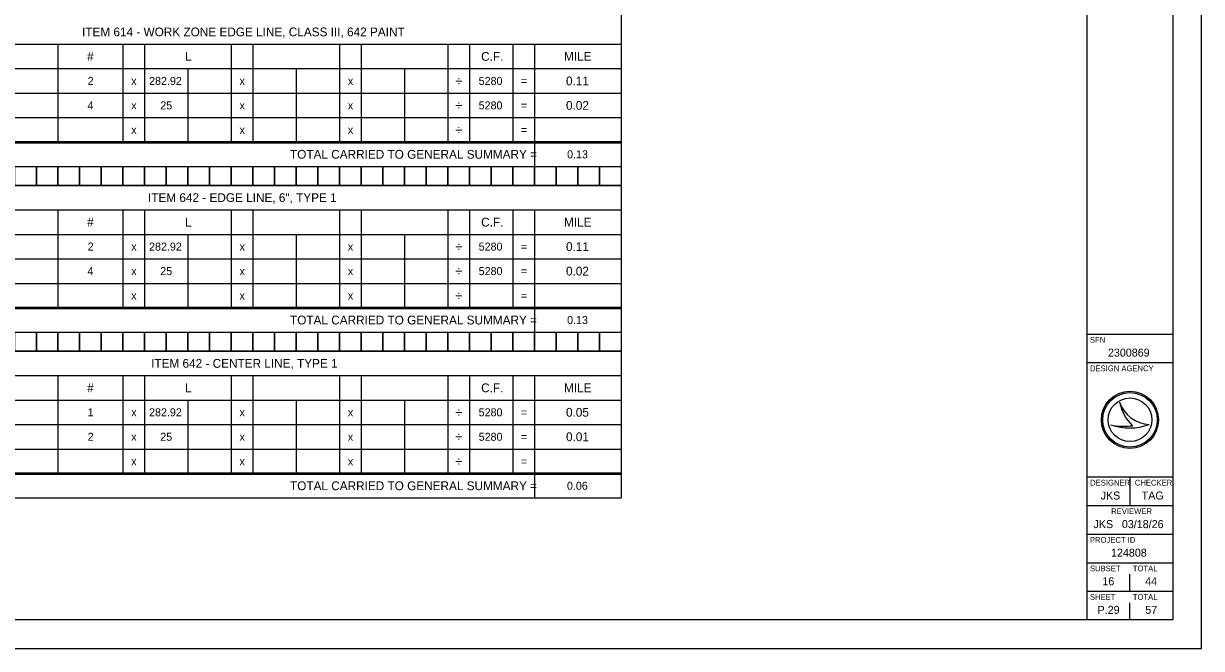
# Model space of a CAD drawing. Extents: x 0 to 34, y 0 to 22.
# Drawn here: x 13.4 to 34, y 0 to 10.93 of the extents above; entities that cross this region are included whole.
import ezdxf

# ---------------------------------------------------------------- set-up
doc = ezdxf.new("R2010")
doc.units = 0
for name, color, linetype in [('Default', 7, 'Continuous'), ('SH_Border', 7, 'Continuous'), ('SH_Cut_Line', 7, 'Continuous'), ('SH_Data', 7, 'Continuous')]:
    doc.layers.add(name, color=color, linetype=linetype)

msp = doc.modelspace()

# ---------------------------------------------------------------- linework, layer by layer
at = {"layer": 'Default'}
for p, q in [((23.854, 11.768), (23.854, 8.847)), ((10.595, 10.571), (23.854, 10.571)), ((14.004, 10.571), (14.004, 8.869)), ((15.141, 10.571), (15.141, 8.869)), ((15.52, 10.571), (15.52, 8.869)), ((17.035, 10.571), (17.035, 8.869)), ((17.414, 10.571), (17.414, 8.869)), ((18.929, 10.571), (18.929, 8.869)), ((19.308, 10.571), (19.308, 8.869)), ((20.823, 10.571), (20.823, 8.869)), ((21.202, 10.571), (21.202, 8.869)), ((21.96, 10.571), (21.96, 8.869)), ((22.339, 10.571), (22.339, 8.869)), ((10.595, 10.143), (23.854, 10.143)), ((16.277, 10.143), (16.277, 8.869)), ((18.171, 10.143), (18.171, 8.869)), ((20.066, 10.143), (20.066, 8.869)), ((10.595, 9.714), (23.854, 9.714)), ((10.595, 9.286), (23.854, 9.286)), ((10.595, 8.869), (23.854, 8.869)), ((23.854, 8.869), (23.854, 5.948)), ((10.595, 8.847), (23.854, 8.847)), ((22.339, 8.847), (22.339, 8.43)), ((10.595, 8.43), (23.854, 8.43)), ((10.595, 8.1), (23.854, 8.1)), ((10.595, 7.672), (23.854, 7.672)), ((14.004, 7.672), (14.004, 5.97)), ((15.141, 7.672), (15.141, 5.97)), ((15.52, 7.672), (15.52, 5.97)), ((17.035, 7.672), (17.035, 5.97)), ((17.414, 7.672), (17.414, 5.97)), ((18.929, 7.672), (18.929, 5.97)), ((19.308, 7.672), (19.308, 5.97)), ((20.823, 7.672), (20.823, 5.97)), ((21.202, 7.672), (21.202, 5.97)), ((21.96, 7.672), (21.96, 5.97)), ((22.339, 7.672), (22.339, 5.97)), ((10.595, 7.244), (23.854, 7.244)), ((16.277, 7.244), (16.277, 5.97)), ((18.171, 7.244), (18.171, 5.97)), ((20.066, 7.244), (20.066, 5.97)), ((10.595, 6.816), (23.854, 6.816)), ((10.595, 6.387), (23.854, 6.387)), ((10.595, 5.97), (23.854, 5.97)), ((10.595, 5.948), (23.854, 5.948)), ((22.339, 5.948), (22.339, 5.531)), ((23.854, 5.97), (23.854, 3.049)), ((10.595, 5.531), (23.854, 5.531)), ((10.595, 5.201), (23.854, 5.201)), ((10.595, 4.773), (23.854, 4.773)), ((14.004, 4.773), (14.004, 3.071)), ((15.141, 4.773), (15.141, 3.071)), ((15.52, 4.773), (15.52, 3.071)), ((17.035, 4.773), (17.035, 3.071)), ((17.414, 4.773), (17.414, 3.071)), ((18.929, 4.773), (18.929, 3.071)), ((19.308, 4.773), (19.308, 3.071)), ((20.823, 4.773), (20.823, 3.071)), ((21.202, 4.773), (21.202, 3.071)), ((21.96, 4.773), (21.96, 3.071)), ((22.339, 4.773), (22.339, 3.071)), ((10.595, 4.345), (23.854, 4.345)), ((16.277, 4.345), (16.277, 3.071)), ((18.171, 4.345), (18.171, 3.071)), ((20.066, 4.345), (20.066, 3.071)), ((10.595, 3.917), (23.854, 3.917)), ((10.595, 3.488), (23.854, 3.488)), ((10.595, 3.071), (23.854, 3.071)), ((10.595, 3.049), (23.854, 3.049)), ((22.339, 3.049), (22.339, 2.632)), ((23.854, 3.071), (23.854, 2.632)), ((10.595, 2.632), (23.854, 2.632))]:
    msp.add_line(p, q, dxfattribs=at)
for points in [[(13.247, 8.43), (13.626, 8.43), (13.626, 8.1), (13.247, 8.1)], [(13.626, 8.43), (14.004, 8.43), (14.004, 8.1), (13.626, 8.1)], [(14.004, 8.43), (14.383, 8.43), (14.383, 8.1), (14.004, 8.1)], [(14.383, 8.43), (14.762, 8.43), (14.762, 8.1), (14.383, 8.1)], [(14.762, 8.43), (15.141, 8.43), (15.141, 8.1), (14.762, 8.1)], [(15.141, 8.43), (15.52, 8.43), (15.52, 8.1), (15.141, 8.1)], [(15.52, 8.43), (15.899, 8.43), (15.899, 8.1), (15.52, 8.1)], [(15.899, 8.43), (16.277, 8.43), (16.277, 8.1), (15.899, 8.1)], [(16.277, 8.43), (16.656, 8.43), (16.656, 8.1), (16.277, 8.1)], [(16.656, 8.43), (17.035, 8.43), (17.035, 8.1), (16.656, 8.1)], [(17.035, 8.43), (17.414, 8.43), (17.414, 8.1), (17.035, 8.1)], [(17.414, 8.43), (17.793, 8.43), (17.793, 8.1), (17.414, 8.1)], [(17.793, 8.43), (18.171, 8.43), (18.171, 8.1), (17.793, 8.1)], [(18.171, 8.43), (18.55, 8.43), (18.55, 8.1), (18.171, 8.1)], [(18.55, 8.43), (18.929, 8.43), (18.929, 8.1), (18.55, 8.1)], [(18.929, 8.43), (19.308, 8.43), (19.308, 8.1), (18.929, 8.1)], [(19.308, 8.43), (19.687, 8.43), (19.687, 8.1), (19.308, 8.1)], [(19.687, 8.43), (20.066, 8.43), (20.066, 8.1), (19.687, 8.1)], [(20.066, 8.43), (20.444, 8.43), (20.444, 8.1), (20.066, 8.1)], [(20.444, 8.43), (20.823, 8.43), (20.823, 8.1), (20.444, 8.1)], [(20.823, 8.43), (21.202, 8.43), (21.202, 8.1), (20.823, 8.1)], [(21.202, 8.43), (21.581, 8.43), (21.581, 8.1), (21.202, 8.1)], [(21.581, 8.43), (21.96, 8.43), (21.96, 8.1), (21.581, 8.1)], [(21.96, 8.43), (22.339, 8.43), (22.339, 8.1), (21.96, 8.1)], [(22.339, 8.43), (22.717, 8.43), (22.717, 8.1), (22.339, 8.1)], [(22.717, 8.43), (23.096, 8.43), (23.096, 8.1), (22.717, 8.1)], [(23.096, 8.43), (23.475, 8.43), (23.475, 8.1), (23.096, 8.1)], [(23.475, 8.43), (23.854, 8.43), (23.854, 8.1), (23.475, 8.1)], [(13.247, 5.531), (13.626, 5.531), (13.626, 5.201), (13.247, 5.201)], [(13.626, 5.531), (14.004, 5.531), (14.004, 5.201), (13.626, 5.201)], [(14.004, 5.531), (14.383, 5.531), (14.383, 5.201), (14.004, 5.201)], [(14.383, 5.531), (14.762, 5.531), (14.762, 5.201), (14.383, 5.201)], [(14.762, 5.531), (15.141, 5.531), (15.141, 5.201), (14.762, 5.201)], [(15.141, 5.531), (15.52, 5.531), (15.52, 5.201), (15.141, 5.201)], [(15.52, 5.531), (15.899, 5.531), (15.899, 5.201), (15.52, 5.201)], [(15.899, 5.531), (16.277, 5.531), (16.277, 5.201), (15.899, 5.201)], [(16.277, 5.531), (16.656, 5.531), (16.656, 5.201), (16.277, 5.201)], [(16.656, 5.531), (17.035, 5.531), (17.035, 5.201), (16.656, 5.201)], [(17.035, 5.531), (17.414, 5.531), (17.414, 5.201), (17.035, 5.201)], [(17.414, 5.531), (17.793, 5.531), (17.793, 5.201), (17.414, 5.201)], [(17.793, 5.531), (18.171, 5.531), (18.171, 5.201), (17.793, 5.201)], [(18.171, 5.531), (18.55, 5.531), (18.55, 5.201), (18.171, 5.201)], [(18.55, 5.531), (18.929, 5.531), (18.929, 5.201), (18.55, 5.201)], [(18.929, 5.531), (19.308, 5.531), (19.308, 5.201), (18.929, 5.201)], [(19.308, 5.531), (19.687, 5.531), (19.687, 5.201), (19.308, 5.201)], [(19.687, 5.531), (20.066, 5.531), (20.066, 5.201), (19.687, 5.201)], [(20.066, 5.531), (20.444, 5.531), (20.444, 5.201), (20.066, 5.201)], [(20.444, 5.531), (20.823, 5.531), (20.823, 5.201), (20.444, 5.201)], [(20.823, 5.531), (21.202, 5.531), (21.202, 5.201), (20.823, 5.201)], [(21.202, 5.531), (21.581, 5.531), (21.581, 5.201), (21.202, 5.201)], [(21.581, 5.531), (21.96, 5.531), (21.96, 5.201), (21.581, 5.201)], [(21.96, 5.531), (22.339, 5.531), (22.339, 5.201), (21.96, 5.201)], [(22.339, 5.531), (22.717, 5.531), (22.717, 5.201), (22.339, 5.201)], [(22.717, 5.531), (23.096, 5.531), (23.096, 5.201), (22.717, 5.201)], [(23.096, 5.531), (23.475, 5.531), (23.475, 5.201), (23.096, 5.201)], [(23.475, 5.531), (23.854, 5.531), (23.854, 5.201), (23.475, 5.201)]]:
    msp.add_lwpolyline(points, close=True, dxfattribs=at)
at = {"layer": 'SH_Border'}
for p, q in [((32, 0.5), (32, 21.5)), ((32, 5.5), (33.5, 5.5)), ((32, 5), (33.5, 5)), ((32, 3), (33.5, 3)), ((32.75, 3), (32.75, 2.5)), ((32, 2.5), (33.5, 2.5)), ((32, 2), (33.5, 2)), ((32, 1.5), (33.5, 1.5)), ((32, 1), (33.5, 1))]:
    msp.add_line(p, q, dxfattribs=at)
msp.add_lwpolyline([(1.5, 21.5), (33.5, 21.5), (33.5, 0.5), (1.5, 0.5)], close=True, dxfattribs=at)
at = {"layer": 'SH_Cut_Line'}
msp.add_lwpolyline([(0, 0), (34, 0), (34, 22), (0, 22)], close=True, dxfattribs=at)
at = {"layer": 'SH_Data'}
for p, q in [((32.567, 4.31), (32.567, 4.31)), ((32.75, 4), (32.75, 4)), ((33.087, 3.919), (33.087, 3.919)), ((32.417, 3.91), (32.417, 3.91)), ((32.75, 1), (32.75, 1.3)), ((32.375, 0.675), (32.375, 0.675)), ((32.75, 0.5), (32.75, 0.8))]:
    msp.add_line(p, q, dxfattribs=at)
for radius in [0.5, 0.477, 0.477, 0.382]:
    msp.add_circle((32.75, 4), radius, dxfattribs=at)
for centre, radius, start, end in [((33.116, 4.498), 0.58, 198.9257, 198.9319), ((33.347, 4.47), 0.796, 191.6379, 191.6421), ((33.116, 4.498), 0.58, 198.9319, 267.1657), ((33.347, 4.47), 0.796, 191.6421, 226.0947), ((32.739, 4.87), 1.013, 251.4576, 290.0832), ((32.648, 5.154), 1.266, 259.4964, 259.4995), ((32.739, 4.87), 1.013, 251.4527, 251.4576), ((32.648, 5.154), 1.266, 259.4995, 276.6672)]:
    msp.add_arc(centre, radius, start, end, dxfattribs=at)

# ---------------------------------------------------------------- texts
at = {"layer": 'Default'}
for s, height, p in [('ITEM 614 - WORK ZONE EDGE LINE, CLASS III, 642 PAINT', 0.154, (14.425, 10.708)), ('#', 0.154, (14.514, 10.28)), ('L', 0.154, (16.227, 10.28)), ('C.F.', 0.154, (21.404, 10.28)), ('MILE', 0.154, (22.853, 10.28)), ('2', 0.14, (14.523, 9.858)), ('x', 0.14, (15.285, 9.858)), ('282.92', 0.14, (15.597, 9.858)), ('x', 0.14, (17.179, 9.858)), ('x', 0.14, (19.073, 9.858)), ('÷', 0.168, (20.951, 9.844)), ('5280', 0.14, (21.361, 9.858)), ('=', 0.14, (22.099, 9.858)), ('0.11', 0.154, (22.888, 9.851)), ('4', 0.14, (14.52, 9.43)), ('x', 0.14, (15.285, 9.43)), ('25', 0.14, (15.793, 9.43)), ('x', 0.14, (17.179, 9.43)), ('x', 0.14, (19.073, 9.43)), ('÷', 0.168, (20.951, 9.416)), ('5280', 0.14, (21.361, 9.43)), ('=', 0.14, (22.099, 9.43)), ('0.02', 0.154, (22.888, 9.423)), ('x', 0.14, (15.285, 9.002)), ('x', 0.14, (17.179, 9.002)), ('x', 0.14, (19.073, 9.002)), ('÷', 0.168, (20.951, 8.988)), ('=', 0.14, (22.099, 9.002)), ('TOTAL CARRIED TO GENERAL SUMMARY =', 0.154, (18.062, 8.567)), ('0.13', 0.14, (22.907, 8.574)), ('ITEM 642 - EDGE LINE, 6", TYPE 1', 0.154, (15.578, 7.809)), ('#', 0.154, (14.514, 7.381)), ('L', 0.154, (16.227, 7.381)), ('C.F.', 0.154, (21.404, 7.381)), ('MILE', 0.154, (22.853, 7.381)), ('2', 0.14, (14.523, 6.96)), ('x', 0.14, (15.285, 6.96)), ('282.92', 0.14, (15.597, 6.96)), ('x', 0.14, (17.179, 6.96)), ('x', 0.14, (19.073, 6.96)), ('÷', 0.168, (20.951, 6.946)), ('5280', 0.14, (21.361, 6.96)), ('=', 0.14, (22.099, 6.96)), ('0.11', 0.154, (22.888, 6.953)), ('4', 0.14, (14.52, 6.531)), ('x', 0.14, (15.285, 6.531)), ('25', 0.14, (15.793, 6.531)), ('x', 0.14, (17.179, 6.531)), ('x', 0.14, (19.073, 6.531)), ('÷', 0.168, (20.951, 6.517)), ('5280', 0.14, (21.361, 6.531)), ('=', 0.14, (22.099, 6.531)), ('0.02', 0.154, (22.888, 6.524)), ('x', 0.14, (15.285, 6.103)), ('x', 0.14, (17.179, 6.103)), ('x', 0.14, (19.073, 6.103)), ('÷', 0.168, (20.951, 6.089)), ('=', 0.14, (22.099, 6.103)), ('TOTAL CARRIED TO GENERAL SUMMARY =', 0.154, (18.062, 5.668)), ('0.13', 0.14, (22.907, 5.675)), ('ITEM 642 - CENTER LINE, TYPE 1', 0.154, (15.633, 4.91)), ('#', 0.154, (14.514, 4.482)), ('L', 0.154, (16.227, 4.482)), ('C.F.', 0.154, (21.404, 4.482)), ('MILE', 0.154, (22.853, 4.482)), ('1', 0.14, (14.523, 4.061)), ('x', 0.14, (15.285, 4.061)), ('282.92', 0.14, (15.597, 4.061)), ('x', 0.14, (17.179, 4.061)), ('x', 0.14, (19.073, 4.061)), ('÷', 0.168, (20.951, 4.047)), ('5280', 0.14, (21.361, 4.061)), ('=', 0.14, (22.099, 4.061)), ('0.05', 0.154, (22.888, 4.054)), ('2', 0.14, (14.523, 3.633)), ('x', 0.14, (15.285, 3.633)), ('25', 0.14, (15.793, 3.633)), ('x', 0.14, (17.179, 3.633)), ('x', 0.14, (19.073, 3.633)), ('÷', 0.168, (20.951, 3.619)), ('5280', 0.14, (21.361, 3.633)), ('=', 0.14, (22.099, 3.633)), ('0.01', 0.154, (22.888, 3.626)), ('x', 0.14, (15.285, 3.204)), ('x', 0.14, (17.179, 3.204)), ('x', 0.14, (19.073, 3.204)), ('÷', 0.168, (20.951, 3.19)), ('=', 0.14, (22.099, 3.204)), ('TOTAL CARRIED TO GENERAL SUMMARY =', 0.154, (18.062, 2.769)), ('0.06', 0.14, (22.905, 2.776))]:
    msp.add_text(s, height=height, dxfattribs=at).set_placement(p)
at = {"layer": 'SH_Data'}
for s, height, p in [('SFN', 0.1, (32.05, 5.35)), ('2300869', 0.14, (32.365, 5.105)), ('DESIGN AGENCY', 0.1, (32.05, 4.85)), ('DESIGNER', 0.1, (32.054, 2.85)), ('CHECKER', 0.1, (32.835, 2.85)), ('JKS', 0.14, (32.237, 2.605)), ('TAG', 0.14, (32.955, 2.605)), ('REVIEWER', 0.1, (32.422, 2.35)), ('JKS', 0.14, (32.112, 2.105)), ('03/18/26', 0.14, (32.609, 2.105)), ('PROJECT ID', 0.1, (32.05, 1.85)), ('124808', 0.14, (32.419, 1.605)), ('SUBSET', 0.1, (32.05, 1.35)), ('TOTAL', 0.1, (32.8, 1.35)), ('16', 0.14, (32.268, 1.105)), ('44', 0.14, (33.016, 1.105)), ('SHEET', 0.1, (32.05, 0.85)), ('TOTAL', 0.1, (32.8, 0.85)), ('P.29', 0.14, (32.184, 0.605)), ('57', 0.14, (33.018, 0.605))]:
    msp.add_text(s, height=height, dxfattribs=at).set_placement(p)

doc.saveas('drawing.dxf')
